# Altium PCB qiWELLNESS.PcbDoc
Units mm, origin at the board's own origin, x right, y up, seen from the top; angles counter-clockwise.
Board outline 74 x 125 mm, 2 copper layers (Top Layer, Bottom Layer); 34 components, 29 nets, 148 pads, 23 vias.
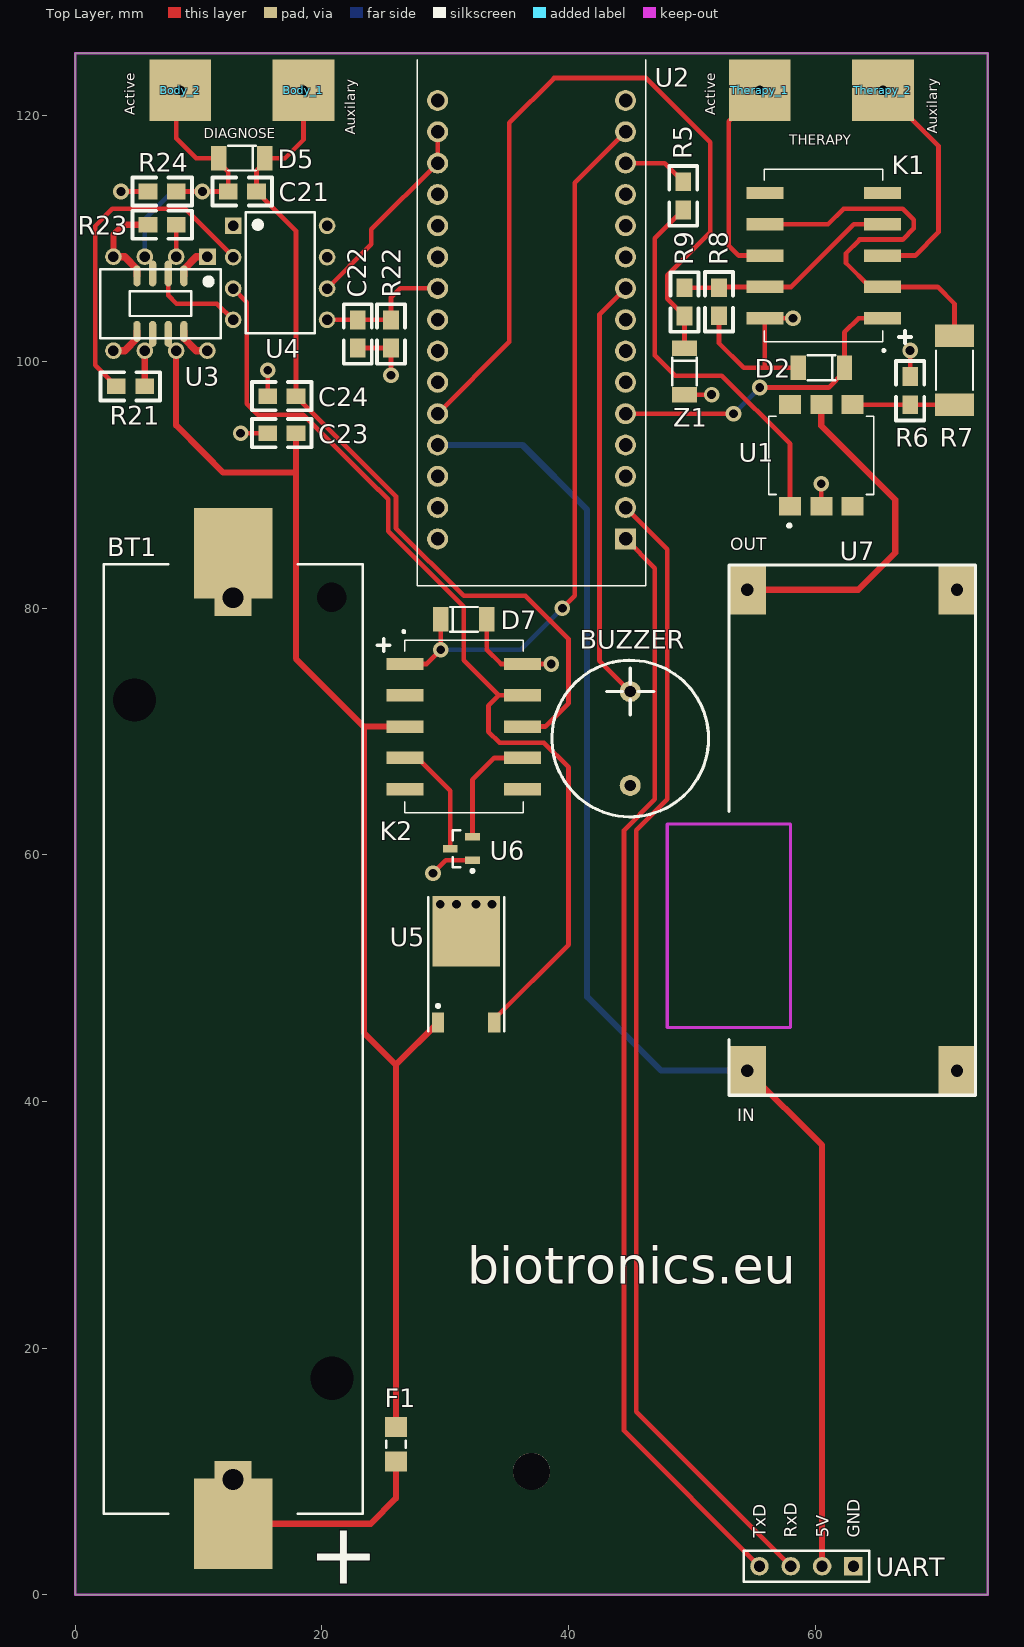
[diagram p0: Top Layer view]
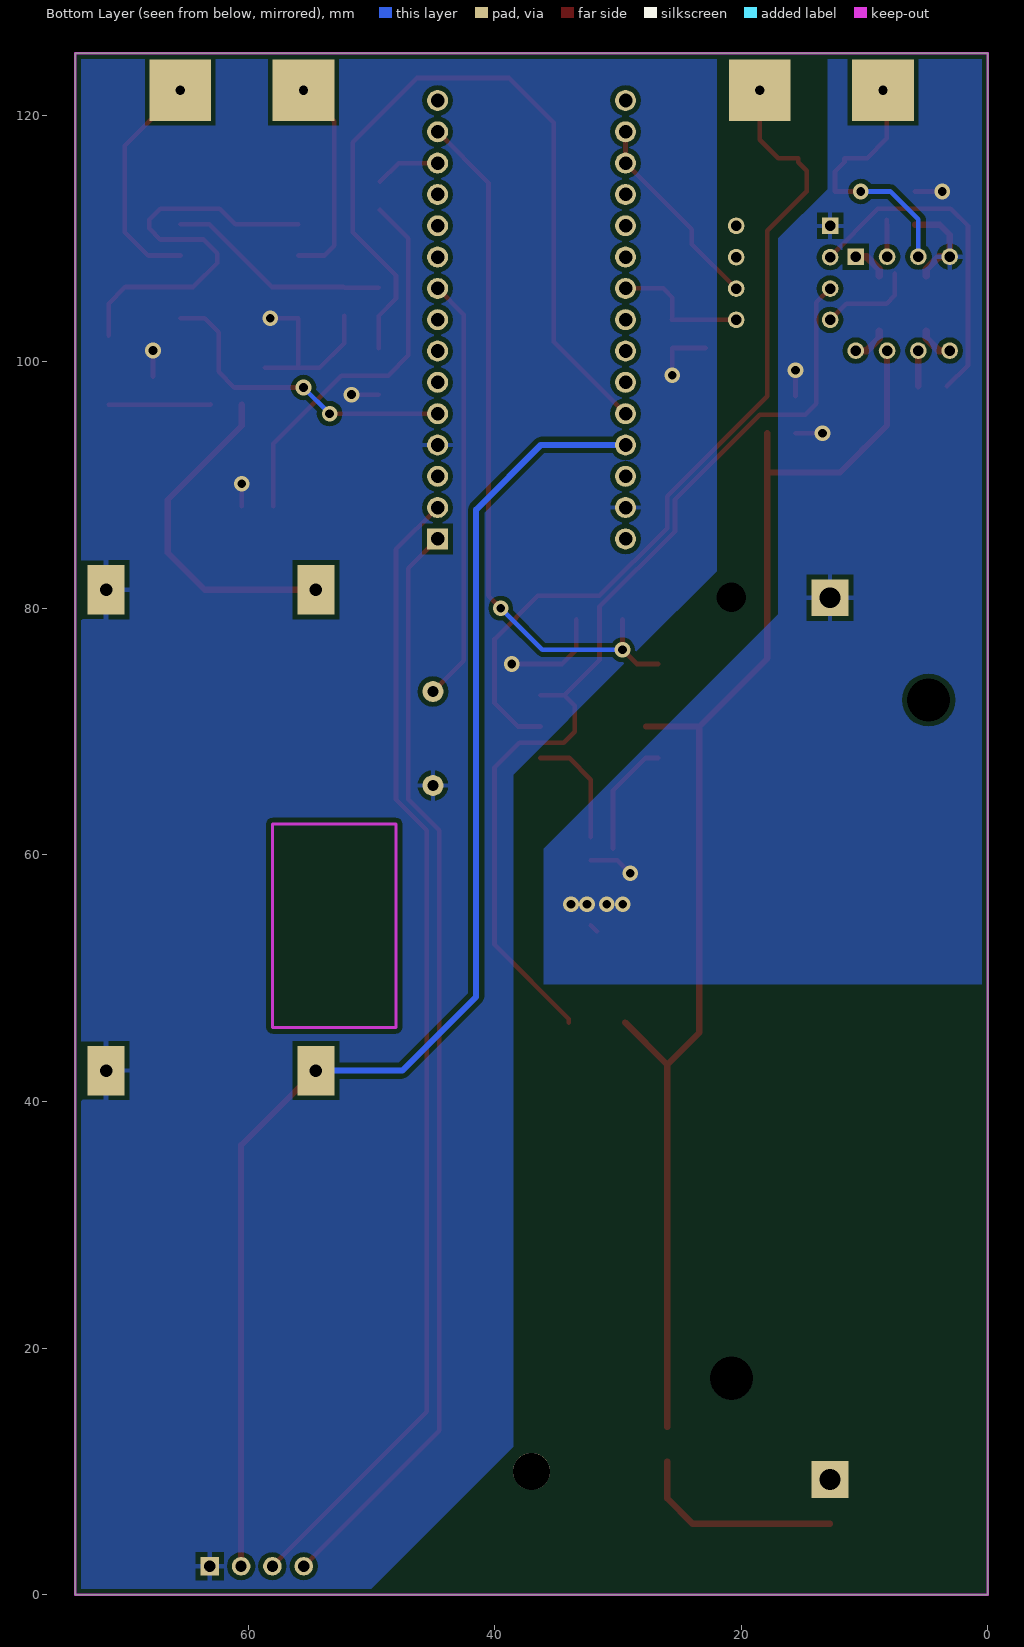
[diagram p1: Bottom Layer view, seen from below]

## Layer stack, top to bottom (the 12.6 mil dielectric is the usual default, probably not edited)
Top Layer: signal copper 0.0356
Dielectric: dielectric 0.32, FR-4, Dk 4.8
Bottom Layer: signal copper 0.0356

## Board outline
0,0 74,0 74,125 0,125

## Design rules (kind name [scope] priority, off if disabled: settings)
Clearance Poly [InPoly] p1: gap=0.381
Clearance [All] p2: gap=0.254
PolygonConnect Via [IsVia] p1: connectstyle=Direct reliefconductorwidth=0.254 reliefentries=4 polygonreliefangle="90 Angle"
PolygonConnect [All] p2: connectstyle=Relief reliefconductorwidth=0.381 reliefentries=4 polygonreliefangle="90 Angle"
RoomDefinition qiWELLNESS [InComponentClass('qiWELLNESS')] p1: confinementstyle=ConfineIn formatcopy=TRUE lockcomponents=FALSE outline 75.057,-1.016 375.793,-1.016 375.793,88.138 75.057,88.138
RoutingVias [All] p1: holewidth=0.381 width=0.762 viastyle="Through Hole" minholewidth=0.711 minwidth=1.27 maxholewidth=0.762 maxwidth=1.524
SolderMaskExpansion [All] p1: expansion=0.102
TestPointUsage [All] p1: valid=0 allowmultiple=FALSE
Testpoint [All] p1: side=15 testpointundercomponent=TRUE minsize=1.016 maxsize=2.54 preferedsize=1.524 minholesize=0 maxholesize=1.016 preferedholesize=0.813 testpointgrid=0.025 style=1023 order=0123456789
Width [All] p1: maxlimit=0.508 minlimit=0.254 preferedwidth=0.254
19 further rules are at their usual default settings.

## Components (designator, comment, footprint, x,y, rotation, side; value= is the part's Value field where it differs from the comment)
Body_1 "Red" PAD 18.5,122 r90 top
Body_2 "Black" PAD 8.5,122 r90 top
BT1 "KEYS1042" KEYS1042 12.8,45.1 r90 top
BUZZER "Buzzer" BUZZER 45,70.7 r90 top (schematic designator LS1)
C21 "1nF/100V" 0805#1 12.4,113.8 r0 top
C22 "10nF" 0805#1 22.9,101.1 r90 top
C23 "100nF" 0805#1 15.6,94.2 r0 top
C24 "100nF" 0805#1 15.6,97.2 r0 top
D2 "LL4148" SOD-80 60.5,99.5 r0 top
D5 "LL4148" SOD-80 13.5,116.5 r0 top
D7 "LL4148" SOD-80 31.5,79.1 r180 top
F1 "0ZCJ0016FF2E" 3216[1206] 26,12.2 r90 top
K1 "RSM850-6112-8M-1005" RELAY_RSM850-6112-8M-1005 60.7,108.6 r90 top
K2 "RSM850-6112-8M-1005" RELAY_RSM850-6112-8M-1005 31.5,70.4 r270 top
R5 "330R" 0805#1 49.3,112.3 r90 top
R6 "22k" 0805#1 67.7,96.5 r90 top
R7 "1k 1W" 1T-2512 71.3,99.3 r90 top
R8 "330R" 0805#1 52.2,106 r270 top
R9 "330R" 0805#1 49.4,103.7 r90 top
R21 "100R" 0805#2 5.6,98 r180 top
R22 "22k" 0805#1 25.6,101.1 r90 top
R23 "33k" 0805#1 5.9,111.1 r0 top
R24 "220k" 0805#1 5.9,113.8 r0 top
Therapy_1 "Black" PAD 55.5,122 r90 top
Therapy_2 "Red" PAD 65.5,122 r90 top
U1 "CNY17-1" OPTOCOUPLER_H11F3SR2M 60.5,92.4 r90 top
U2 "A000005" ARDUINO_A000005 37,103.4 r180 top locked
U3 "MCP6141-E/SN" DIP_SOP_8 6.9,104.7 r270 top
U4 "IL300" DIP8 16.6,107.2 r0 top
U5 "LP2950CDT-3.3" 369A-13 31.7,50.1 r0 top
U6 "MCP1700T-1202E/TT" SOT-23-TT3_L 31.3,60.5 r180 top
U7 "XL6009E1" XL6009E1 73,40.5 r90 top locked
UART "Header 4" HDR1X4 63.1,2.3 r180 top (schematic designator P1)
Z1 "3V3" SOD-80 49.4,99.2 r90 top

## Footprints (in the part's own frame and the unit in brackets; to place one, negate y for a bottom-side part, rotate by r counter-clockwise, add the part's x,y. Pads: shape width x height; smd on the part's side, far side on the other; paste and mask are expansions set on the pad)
1T-2512 [mm] "Chip Resistor; Body 6.4 x 3.2 mm (LxW typ)"
  rect 1.8x3.2 smd: 1(-2.8,0) 2(2.8,0)
  silkscreen extent -1.6,-1.5 1.6,1.5
369A-13 [mm] "D-PAK/TO-252-AA; 3 Leads (1 Cropped); Body 10.3 (inc. leads) x 6.7 mm (LxW max)"
  rect 1x1.6 smd: 1(-2.285,-3.7) 3(2.285,-3.7)
  rect 5.5x5.7 smd: 4(0,3.7)
  silkscreen extent -3.09,-4.4 3.09,6.45
0805#1 [mil] "without overlay"
  rect 60x50 smd: 1(0,0) 2(90,0)
  silkscreen extent -50,-45 140,45
0805#2 [mil] "without overlay"
  rect 60x50 smd: 1(-1.18,0) 2(90,0)
  silkscreen extent -50,-45 140,45
3216[1206] [mm] "Chip Resistor; Body 3.2 x 1.6 mm (LxW typ)"
  rect 1.6x1.8 smd: 1(-1.4,0) 2(1.4,0)
  silkscreen extent -0.3,-0.8 0.3,0.8
ARDUINO_A000005 [mm] "NANO"
  rect 1.7x1.7 hole 1.1: 1(-7.62,17.78)
  round 1.7 hole 1.1: 2(-7.62,15.24) 3(-7.62,12.7) 4(-7.62,10.16) 5(-7.62,7.62) 6(-7.62,5.08) 7(-7.62,2.54) 8(-7.62,0) 9(-7.62,-2.54) 10(-7.62,-5.08) 11(-7.62,-7.62) 12(-7.62,-10.16) 13(-7.62,-12.7) 14(-7.62,-15.24) 15(-7.62,-17.78) 16(7.62,-17.78) 17(7.62,-15.24) 18(7.62,-12.7) 19(7.62,-10.16) 20(7.62,-7.62) 21(7.62,-5.08) 22(7.62,-2.54) 23(7.62,0) 24(7.62,2.54) 25(7.62,5.08) 26(7.62,7.62) 27(7.62,10.16) 28(7.62,12.7) 29(7.62,15.24) 30(7.62,17.78)
  silkscreen extent -9.27,-21.1 9.27,21.59
BUZZER [mm]
  round 1.7 hole 0.9: 1(2.54,0) 2(-5.08,0)
  silkscreen extent -7.62,-6.35 5.08,6.35
DIP8 [mm]
  rect 1.35x1.35 hole 0.85: 1(-3.81,3.81)
  round 1.35 hole 0.85: 2(-3.81,1.27) 3(-3.81,-1.27) 4(-3.81,-3.81) 5(3.81,-3.81) 6(3.81,-1.27) 7(3.81,1.27) 8(3.81,3.81)
  silkscreen extent -2.8,-4.9 2.8,4.9
DIP_SOP_8 [mm]
  rect 1.35x1.35 hole 0.85: 1(-3.81,3.81)
  oval 1.7x0.6 smd: 1(-2.25,1.905) 4(-2.25,-1.905) 5(2.25,-1.905) 8(2.25,1.905)
  round 1.35 hole 0.85: 2(-3.81,1.27) 3(-3.81,-1.27) 4(-3.81,-3.81) 5(3.81,-3.81) 6(3.81,-1.27) 7(3.81,1.27) 8(3.81,3.81)
  oval 2.1x0.6 smd: 2(-2.45,0.635) 3(-2.45,-0.635) 6(2.45,-0.635) 7(2.45,0.635)
  Top Layer lines w0.6: 3.81,-3.81 3.81,-2.91 2.805,-1.905 2.25,-1.905 ; -3.81,-3.81 -3.81,-2.91 -2.805,-1.905 -2.25,-1.905 ; 2.25,1.905 2.805,1.905 3.81,2.91 3.81,3.81 ; -2.25,1.905 -2.805,1.905 -3.81,2.91 -3.81,3.81
  silkscreen extent -2.8,-4.9 2.8,4.9, body extent -2,-2.5 2,2.5, height 1.75
HDR1X4 [mm] "Connector; Header; 4 Position"
  rect 1.5x1.5 hole 0.9: 1(0,0)
  round 1.5 hole 0.9: 2(2.54,0) 3(5.08,0) 4(7.62,0)
  silkscreen extent -1.27,-1.27 8.89,1.27
KEYS1042 [mm]
  rect 0x0 hole 3.5: 0(-27.55,-8) 0(27.45,8)
  rect 0x0 hole 2.4: 0(35.78,-8)
  rect 7.34x6.35 smd: 1(-39.35,0) 2(39.35,0)
  rect 3x3 hole 1.7: 1(-35.75,0) 2(35.75,0)
  silkscreen extent -38.55,-10.5 38.45,10.5
OPTOCOUPLER_H11F3SR2M [mm]
  rect 1.52x1.78 smd: 1(-4.125,2.54) 2(-4.125,0) 3(-4.125,-2.54) 4(4.125,-2.54) 5(4.125,0) 6(4.125,2.54)
  silkscreen extent -5.8,-4.26 3.18,4.26
PAD [mm]
  rect 5x5 smd: 1(0,0)
  rect 5x5 smd far side: 1(0,0)
RELAY_RSM850-6112-8M-1005 [mm]
  rect 1x3 smd: 1(-5.08,-4.78) 2(-2.54,-4.78) 3(0,-4.78) 4(2.54,-4.78) 5(5.08,-4.78) 6(5.08,4.78) 7(2.54,4.78) 8(0,4.78) 9(-2.54,4.78) 10(-5.08,4.78)
  silkscreen extent -7.8,-4.97 7,4.82
SOD-80 [mm]
  rect 1.25x2 smd: 1(-1.875,0) 2(1.875,0)
  silkscreen extent -1.12,-1 1.12,1
SOT-23-TT3_L [mm] "SOT23, 3-Leads, Body 2.9x1.3mm, Pitch 0.95mm, Lead Span 2.4mm, IPC High Density"
  rect 1.2x0.6 smd: 1(-0.9,0.95) 2(-0.9,-0.95) 3(0.9,0)
  silkscreen extent -1.02,-1.5 0.7,1.92, body extent -0.7,-1.5 0.7,1.5, height 1.12
XL6009E1 [mm]
  rect 4x3 hole 1: 1(2,18.5) 2(2,1.5) 3(41,1.5) 4(41,18.5)
  silkscreen extent 0,0 43,20

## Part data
Body_1 Body_2 Therapy_1 Therapy_2: library part Plug, "Plug"
BT1: library part Battery, "18650 Battery"
BUZZER: library part SPEAKER, "Buzzer 5V"
C21 C22 C23 C24: library part Cap, "Capacitor"
D2 D5 D7 Z1: library part DIODE, "Switching Diode"
F1: library part "Fuse 2", "Fuse"
K1 K2: library part 1-1462033-4
R5 R6 R8 R9 R21 R22 R23 R24: library part Res1, "Chip Resistor 5% 0.1W"
R7: library part ERJ1T, "Thick Film Chip Resistor, 1 Ohm to 1M Ohm Range, 5% Tolerance, 2512 Size, 1 W"
U1: "CNY17 Series Single Channel 70 V 5000 Vrms Phototransistor Optocoupler - DIP-6"
U2: "MICRO, ARDUINO NANO 3.0, MINI-B USB, ATmega328, 0.1DIP, ICSP HDR"
U3: "600 nA, Non-Unity Gain Rail-to-Rail Input/Output Operational Amplifier, 8-Pin SOIC, Extended Temperature"
U4: "IL300 Series Single Channel 5300 Vrms Wide Bandwidth Linear Optocoupler - DIP-8"
U5: "MicroPower Voltage Regulator"
U6: "Low Quiescent Current LDO, 3-Pin SOT-23, Extended Temperature, Tape and Reel"
U7: "Step-Up OUT 5V-40V"
UART: "Header, 4-Pin"

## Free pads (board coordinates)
  round 3 hole 3: 0(37,10)

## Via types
v1: diameter 1.27, hole 0.711, Top Layer to Bottom Layer, 19 vias
v2: diameter 1.524, hole 0.762, Top Layer to Bottom Layer, 4 vias

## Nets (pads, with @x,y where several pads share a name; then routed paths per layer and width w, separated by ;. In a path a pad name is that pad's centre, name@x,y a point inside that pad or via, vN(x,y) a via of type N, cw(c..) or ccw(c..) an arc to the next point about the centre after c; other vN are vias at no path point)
EAV+(3V7): C23.2 F1.2 K2.3 U3.7 U5.1 | length 111.2
  Top Layer w0.508: U3.7@8.1,101 8.1,100.96 8.17,100.89 8.17,94.83 10.43,92.57 ; 10,93 10.43,92.57 ; C23.2 17.886,91 ; F1.2 26,42.985 ; K2.3@27.7,70.4 K2.3 23.4,70.4 ; U5.1 26,42.985 ; 10.43,92.57 12,91 17.886,91 ; 17.886,91 17.886,75.914 23.4,70.4 ; 23.4,70.4 23.4,45.585 26,42.985
EAV-: BT1.2 C23.1 C24.1 R23.1 R24.1 U3.4 U4.1 U5.4 U6.1 | length 15.8
  Top Layer w0.381: v1(3.7,113.8) R24.1 ; v1(13.4,94.2) C23.1 ; C24.1 v1(15.6,99.3) ; v1(29,58.5) 30.05,59.55 U6.1 ; U5.4 U5.4@32.2,54.3
  Top Layer w0.508: U3.4@3.09,108.51 3.09,110.29 3.9,111.1 R23.1
  other v1: 29.6,56 30.9,56 32.5,56 33.8,56
EAV/VEG: Body_1.1 C21.2 C24.2 D5.2 K2.8 | length 70.2
  Top Layer w0.381: v2(18.5,122) 18.5,118 17,116.5 D5.2 15.375,116.175 14.686,115.486 C21.2 17.886,110.6 C24.2 26,89.086 26,86.5 31.5,81 36.5,81 40,77.5 40,72.3 38.1,70.4 K2.8
GND: BUZZER.2 C22.1 D2.1 D7.1 K1.10 K2.10 R6.2 R8.2 R22.1 U1.2 U2.4 U2.29 U7.2 U7.3 UART.1 Z1.1 | length 35
  Top Layer w0.381: C22.1 R22.1 v1(25.6,98.9) ; D7.1 33.375,76.625 34.52,75.48 K2.10 v1(38.6,75.48) ; Z1.1 v1(51.6,97.325) ; R8.2 52.2,101.5 54.2,99.5 55.9,99.5 ; K1.10 55.92,99.52 55.9,99.5 ; K1.10 v1(58.2,103.52) ; D2.1 55.9,99.5 ; U1.2 v1(60.5,90.1) ; R6.2 v1(67.7,100.9)
NetBody_2_1: Body_2.1 C21.1 D5.1 R24.2 U3.3 | length 24
  Top Layer w0.381: R24.2 v1(10.3,113.8) C21.1 12.4,115.4 11.625,116.175 D5.1 9.786,116.5 8.186,118.1 8.186,121.686 v2(8.5,122)
  Bottom Layer w0.381: U3.3@5.63,108.51 5.63,111.53 7.9,113.8 v1(10.3,113.8)
NetBT1_1: BT1.1 F1.1 | length 17
  Top Layer w0.508: BT1.1@12.8,5.75 23.95,5.75 26,7.8 F1.1
NetBUZZER_1: BUZZER.1 U2.9 | length 34.6
  Top Layer w0.381: U2.9 42.5,103.82 42.5,75.74 BUZZER.1
NetC22_2: C22.2 R22.2 U2.22 U4.5 | length 11.1
  Top Layer w0.381: U4.5 20.414,103.386 C22.2 R22.2 ; R22.2@25.614,103.4 R22.2 ; U2.22 26.34,105.94 25.6,105.2 R22.2
NetD2_2: D2.2 K1.1 U2.5 | length 25.9
  Top Layer w0.381: U2.5 v1(53.38,95.78) ; v1(55.5,97.9) 61.1,97.9 62.375,99.175 D2.2 62.375,102.375 63.52,103.52 K1.1
  Bottom Layer w0.381: v1(53.38,95.78) v1(55.5,97.9)
NetD7_2: D7.2 K2.1 U2.14 | length 57.9
  Top Layer w0.381: K2.1 28.48,75.48 v1(29.625,76.625) D7.2 ; v1(39.5,80) 40.5,81 40.5,114.52 U2.14
  Bottom Layer w0.381: v1(29.625,76.625) 36.125,76.625 v1(39.5,80)
NetK1_2: K1.2 K1.7 R7.2 | length 33.6
  Top Layer w0.381: K1.7 61.04,111.14 62.3,112.4 67.1,112.4 68,111.5 68,110.8 67.1,109.9 63.6,109.9 62.5,108.8 62.5,108 64.44,106.06 K1.2 69.94,106.06 71.3,104.7 R7.2
NetK1_3: K1.3 Therapy_2.1 | length 18.7
  Top Layer w0.381: K1.3 68.1,108.6 70,110.5 70,117.5 v2(65.5,122)
NetK1_4: K1.4 K1.9 R8.1 R9.2 | length 18.2
  Top Layer w0.381: R9.2 52.186,105.986 R8.1 52.26,106.06 K1.9 58.06,106.06 63.14,111.14 K1.4
NetK1_8: K1.8 Therapy_1.1 | length 16.9
  Top Layer w0.381: v2(55.5,122) 53,119.5 53,109.4 53.8,108.6 K1.8
NetK2_4: K2.4 U6.3 | length 9.5
  Top Layer w0.381: K2.4 27.74,67.86 30.4,65.2 U6.3
NetK2_7: K2.7 U6.2 | length 9.5
  Top Layer w0.381: U6.2 32.2,66.1 33.96,67.86 K2.7
NetK2_9: K2.9 U4.3 U5.3 | length 81.6
  Top Layer w0.381: U4.3 13.909,104.81 13.909,96.591 14.8,95.7 18.488,95.7 23.974,90.214 ; 24.994,89.194 23.974,90.214 ; U5.3 33.985,46.685 40,52.7 40,67.1 38,69.1 34.4,69.1 33.5,70 33.5,72.1 34.34,72.94 ; K2.9 34.34,72.94 ; 23.974,90.214 25.365,88.823 25.365,86.237 31.5,80.102 31.5,75.78 34.34,72.94
NetR5_1: R5.1 U1.1 | length 31.7
  Top Layer w0.381: R5.1 47,110 47,100.5 48.635,98.865 52.435,98.865 57.96,93.34 U1.1
NetR5_2: R5.2 U2.13 | length 5.3
  Top Layer w0.381: U2.13 47.786,116.1 R5.2
NetR6_1: R6.1 R7.1 U1.4 | length 8.3
  Top Layer w0.381: U1.4 63.065,96.5 R6.1 R7.1
NetR9_1: R9.1 U2.26 Z1.2 | length 64.7
  Top Layer w0.381: U2.26 35.2,101.6 35.2,119.38 38.82,123 46.3,123 51.5,117.8 51.5,110.5 48,107 48,105.1 R9.1 Z1.2
NetR21_1: R21.1 U3.6 | length 2.9
  Top Layer w0.508: R21.1 U3.6@5.63,100.89
NetR21_2: R21.2 U4.2 | length 27.1
  Top Layer w0.381: R21.2 1.6,99.714 1.6,111 3,112.4 8.912,112.4 12.79,108.522 U4.2
NetR23_2: R23.2 U3.2 U4.4 | length 10.9
  Top Layer w0.381: U3.2@7.535,107.15 7.535,105.365 8.2,104.7 11.48,104.7 U4.4 ; U3.2@8.17,108.51 8.17,111.084 R23.2 R23.2@8.186,111.5
NetU1_5: U1.5 U7.4 | length 27.8
  Top Layer w0.508: U7.4 63.5,81.5 66.5,84.5 66.5,88.8 60.5,94.8 U1.5
NetU2_1: U2.1 UART.4 | length 89.9
  Top Layer w0.381: U2.1 47,83.24 47,64.5 44.5,62 44.5,13.28 UART.4
NetU2_2: U2.2 UART.3 | length 93.5
  Top Layer w0.381: U2.2 48,84.78 48,64.5 45.5,62 45.5,14.82 UART.3
NetU2_17: U2.17 U2.18 U4.6 | length 16.4
  Top Layer w0.381: U4.6 24,109.52 24,110.72 U2.18 U2.17
NetU2_27: U2.27 U7.1 UART.2 | length 112
  Top Layer w0.508: U7.1 60.56,36.44 UART.2
  Bottom Layer w0.508: U2.27 36.26,93.24 41.5,88 41.5,48.5 47.5,42.5 U7.1
pads on no net: BT1.0 K1.5 K1.6 K2.2 K2.5 K2.6 U1.3 U1.6 U2.3 U2.6 U2.7 U2.8 U2.10 U2.11 U2.12 U2.15 U2.16 U2.19 U2.20 U2.21 U2.23 U2.24 U2.25 U2.28 U2.30 U3.1 U3.5 U3.8 U4.7 U4.8

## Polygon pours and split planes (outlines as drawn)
GND on Bottom Layer "Bottom Layer-No Net" (solid, remove dead copper, pour order 1001): 22,125 22,117.5 22,83 38.5,66.5 38.5,63 38.5,12 50.5,0 74,0 74,125
EAV- on Bottom Layer "Bottom Layer-No Net" (solid, pour order 1000): 0,125 13,125 13,114 17,110 17,99.5 17,79.5 36,60.5 36,56.5 36,49.5 32.5,49.5 0,49.5

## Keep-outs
Keep-Out Layer:
  lines w0.203: 0,0 0,125 74,125 74,1.61 74,0 0,0
  lines w0.254: 48,46 48,62.5 58,62.5 58,46 53,46 48,46
  text "HOLE" at 51,54 h1

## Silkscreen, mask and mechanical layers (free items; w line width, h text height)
Top Overlay:
  lines w0.3: 24.5,77 25.5,77 ; 25,76.5 25,77.5 ; 66.78,102 67.78,102 ; 67.28,101.5 67.28,102.5
  text "Active" at 4.8,120 h0.8 r90
  text "Active" at 51.9,120 h0.8 r90
  text "Auxilary" at 69.9,118.5 h0.8 r90
  text "Auxilary" at 22.7,118.4 h0.8 r90
  text "DIAGNOSE" at 10.4,118.1 h0.8
  text "THERAPY" at 57.9,117.6 h0.8
  text "OUT" at 53.1,84.7 h1
  text "IN" at 53.7,38.4 h1
  text "biotronics.eu" at 31.8,25.2 h3
  text "TxD" at 56,4.6 h1 r90
  text "RxD" at 58.5,4.6 h1 r90
  text "5V" at 61.1,4.6 h1 r90
  text "GND" at 63.6,4.6 h1 r90
  text "+" at 18.9,0.9 h5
